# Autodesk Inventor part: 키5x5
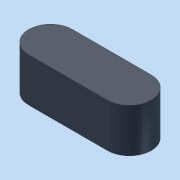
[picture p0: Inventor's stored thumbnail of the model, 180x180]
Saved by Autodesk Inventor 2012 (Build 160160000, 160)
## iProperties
Company: 한국ATC센터
Created: 2014-12
Part Number: 키5x5
Document SubType Name: Modeling
Designer: KYOUNG IL JANG
Density: 1 g/cm^3
Mass: 0.323175 g
Surface Area: 2.9781 cm^2
Volume: 0.323175 cm^3
Material: 기본값
Author: KYOUNG IL JANG
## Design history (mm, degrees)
sketch "스케치1"
  geometry: L1 (-4.5, -2.5)-(4.5, -2.5) reference; L2 (4.5, 2.5)-(-4.5, 2.5) reference; A1 r 2.5 centre (-4.5, 0) between (-4.5, 2.5) and (-4.5, -2.5) reference; A2 r 2.5 centre (4.5, 0) between (4.5, -2.5) and (4.5, 2.5) reference; 1 further point
extrude "돌출1" new body sketch "스케치1" distance "d0" = 5; taper "d1" = 0 deg
node "솔리드1"
node "참조1"
